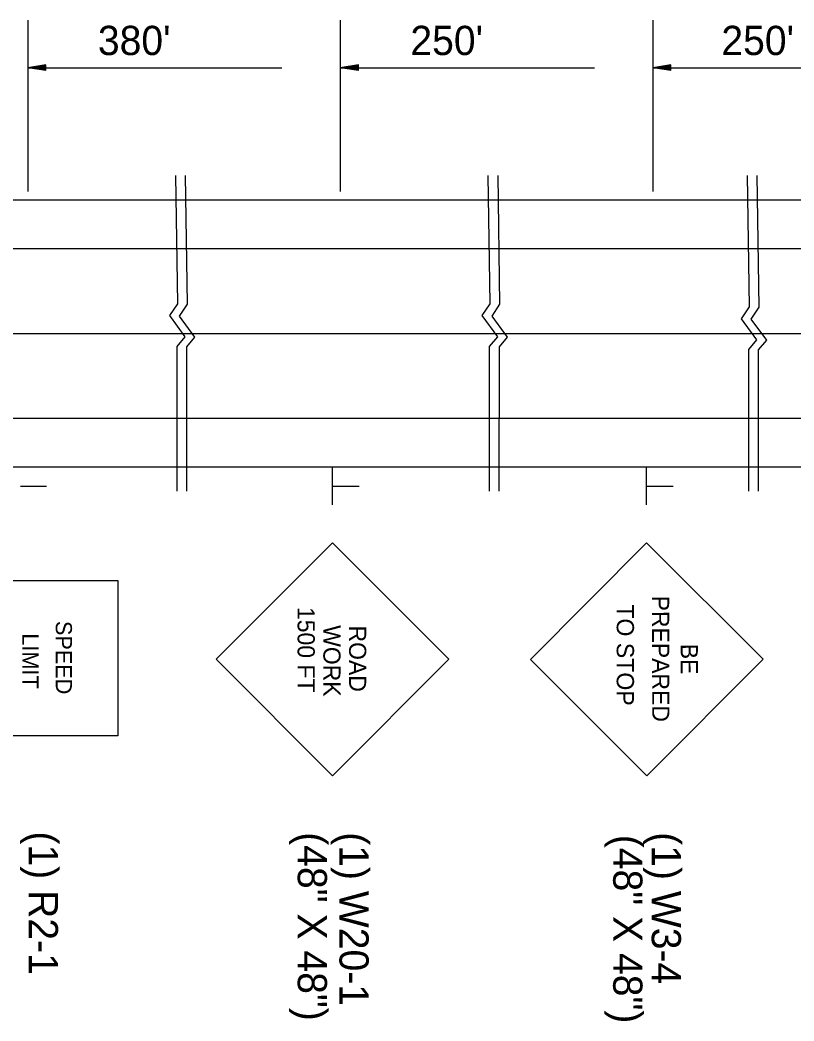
# Model space of a CAD drawing. Extents: x 1678017 to 1687792, y 404433 to 413488.
# Drawn here: x 1680083.5 to 1680242.5, y 405049.7 to 405255.1 of the extents above; entities that cross this region are included whole.
import ezdxf

# ---------------------------------------------------------------- set-up
doc = ezdxf.new("R2010")
doc.units = 0
doc.layers.add('Default', color=7, linetype='Continuous')

msp = doc.modelspace()

# ---------------------------------------------------------------- linework, layer by layer
at = {"layer": 'Default'}
for p, q in [((1680085.13, 405255.07), (1680085.13, 405219.86)), ((1680149.29, 405255.07), (1680149.29, 405219.86)), ((1680213.45, 405255.07), (1680213.45, 405219.86)), ((1680088.88, 405245.84), (1680085.13, 405245.28)), ((1680085.13, 405245.28), (1680137.32, 405245.28)), ((1680088.88, 405244.71), (1680085.13, 405245.28)), ((1680088.88, 405245.74), (1680085.75, 405245.28)), ((1680088.88, 405244.81), (1680085.75, 405245.28)), ((1680088.88, 405245.65), (1680086.4, 405245.28)), ((1680088.88, 405244.9), (1680086.4, 405245.28)), ((1680088.88, 405245.56), (1680087.02, 405245.28)), ((1680088.88, 405245), (1680087.02, 405245.28)), ((1680088.88, 405245.46), (1680087.66, 405245.28)), ((1680088.88, 405245.09), (1680087.66, 405245.28)), ((1680088.88, 405245.36), (1680088.29, 405245.28)), ((1680088.88, 405245.19), (1680088.29, 405245.28)), ((1680088.88, 405244.71), (1680088.88, 405245.84)), ((1680153.04, 405245.84), (1680149.29, 405245.28)), ((1680149.29, 405245.28), (1680201.48, 405245.28)), ((1680153.04, 405244.71), (1680149.29, 405245.28)), ((1680153.04, 405245.74), (1680149.91, 405245.28)), ((1680153.04, 405244.81), (1680149.91, 405245.28)), ((1680153.04, 405245.65), (1680150.56, 405245.28)), ((1680153.04, 405244.9), (1680150.56, 405245.28)), ((1680153.04, 405245.56), (1680151.18, 405245.28)), ((1680153.04, 405245), (1680151.18, 405245.28)), ((1680153.04, 405245.46), (1680151.82, 405245.28)), ((1680153.04, 405245.09), (1680151.82, 405245.28)), ((1680153.04, 405245.36), (1680152.45, 405245.28)), ((1680153.04, 405245.19), (1680152.45, 405245.28)), ((1680153.04, 405244.71), (1680153.04, 405245.84)), ((1680217.2, 405245.84), (1680213.45, 405245.28)), ((1680213.45, 405245.28), (1680265.64, 405245.28)), ((1680217.2, 405244.71), (1680213.45, 405245.28)), ((1680217.2, 405245.74), (1680214.08, 405245.28)), ((1680217.2, 405244.81), (1680214.08, 405245.28)), ((1680217.2, 405245.65), (1680214.72, 405245.28)), ((1680217.2, 405244.9), (1680214.72, 405245.28)), ((1680217.2, 405245.56), (1680215.34, 405245.28)), ((1680217.2, 405245), (1680215.34, 405245.28)), ((1680217.2, 405245.46), (1680215.98, 405245.28)), ((1680217.2, 405245.09), (1680215.98, 405245.28)), ((1680217.2, 405245.36), (1680216.61, 405245.28)), ((1680217.2, 405245.19), (1680216.61, 405245.28)), ((1680217.2, 405244.71), (1680217.2, 405245.84)), ((1679931.89, 405218.16), (1680990.24, 405218.16)), ((1679931.89, 405208.16), (1680480.65, 405208.16)), ((1679931.89, 405190.77), (1680368.2, 405190.77)), ((1679931.89, 405173.39), (1680480.65, 405173.39)), ((1679931.89, 405163.39), (1680990.24, 405163.39)), ((1680147.7, 405155.57), (1680147.7, 405163.39)), ((1680212.19, 405155.57), (1680212.19, 405163.39)), ((1680083.66, 405159.46), (1680089, 405159.46)), ((1680147.82, 405159.46), (1680153.16, 405159.46)), ((1680212.3, 405159.46), (1680217.64, 405159.46)), ((1680123.82, 405123.92), (1680147.7, 405147.83)), ((1680171.61, 405123.92), (1680147.7, 405147.83)), ((1680188.33, 405123.88), (1680212.19, 405147.83)), ((1680236.11, 405123.96), (1680212.19, 405147.83)), ((1680147.7, 405100.02), (1680123.82, 405123.92)), ((1680147.7, 405100.02), (1680171.61, 405123.92)), ((1680212.27, 405100.02), (1680188.33, 405123.88)), ((1680212.27, 405100.02), (1680236.11, 405123.96))]:
    msp.add_line(p, q, dxfattribs=at)
for points in [[(1680115.46, 405223.16), (1680115.86, 405196.83), (1680114.24, 405194.42), (1680117.4, 405190.09), (1680115.74, 405188.09), (1680115.73, 405158.39)], [(1680117.46, 405223.16), (1680117.86, 405196.75), (1680116.24, 405194.33), (1680119.4, 405190), (1680117.74, 405188), (1680117.73, 405158.39)], [(1680179.62, 405223.16), (1680180.03, 405196.83), (1680178.4, 405194.42), (1680181.57, 405190.09), (1680179.9, 405188.09), (1680179.89, 405158.39)], [(1680181.62, 405223.16), (1680182.02, 405196.75), (1680180.4, 405194.33), (1680183.56, 405190), (1680181.9, 405188), (1680181.89, 405158.39)], [(1680232.84, 405223.16), (1680233.25, 405196.2), (1680231.63, 405193.78), (1680234.79, 405189.46), (1680233.12, 405187.46), (1680233.12, 405158.39)], [(1680234.84, 405223.16), (1680235.25, 405196.12), (1680233.62, 405193.7), (1680236.79, 405189.37), (1680235.12, 405187.37), (1680235.12, 405158.39)]]:
    msp.add_lwpolyline(points, dxfattribs=at)
msp.add_lwpolyline([(1680103.63, 405108.19), (1680063.46, 405108.19), (1680063.46, 405140.06), (1680103.63, 405140.06)], close=True, dxfattribs=at)

# ---------------------------------------------------------------- texts
for s, p in [("380'", (1680099.54, 405247.88)), ("250'", (1680163.7, 405247.88)), ("250'", (1680227.55, 405247.88))]:
    msp.add_text(s, height=6, dxfattribs=at).set_placement(p)
for s, height, rotation, p in [('PREPARED', 3.521, 270.1003, (1680213.31, 405136.96)), ('1500 FT', 3.522, 270.0006, (1680140.54, 405134.64)), ('TO STOP', 3.544, 270.0006, (1680206.06, 405135.18)), ('SPEED', 3.32, 270, (1680090.89, 405131.77)), ('WORK', 3.52, 270, (1680145.83, 405130.9)), ('ROAD', 3.521, 270.0004, (1680151.11, 405130.83)), ('LIMIT', 3.32, 270, (1680084.03, 405129.22)), ('BE', 3.521, 270.1004, (1680219.2, 405127.08)), ('(1) R2-1', 6, 270, (1680085.35, 405088.59)), ('(48" X 48")', 6, 270, (1680140.57, 405088.43)), ('(1) W20-1', 6, 270, (1680149.13, 405088.43)), ('(48" X 48")', 6, 270, (1680205.34, 405087.9)), ('(1) W3-4', 6, 270, (1680213.24, 405088.43))]:
    msp.add_text(s, height=height, rotation=rotation, dxfattribs=at).set_placement(p)

doc.saveas('drawing.dxf')
